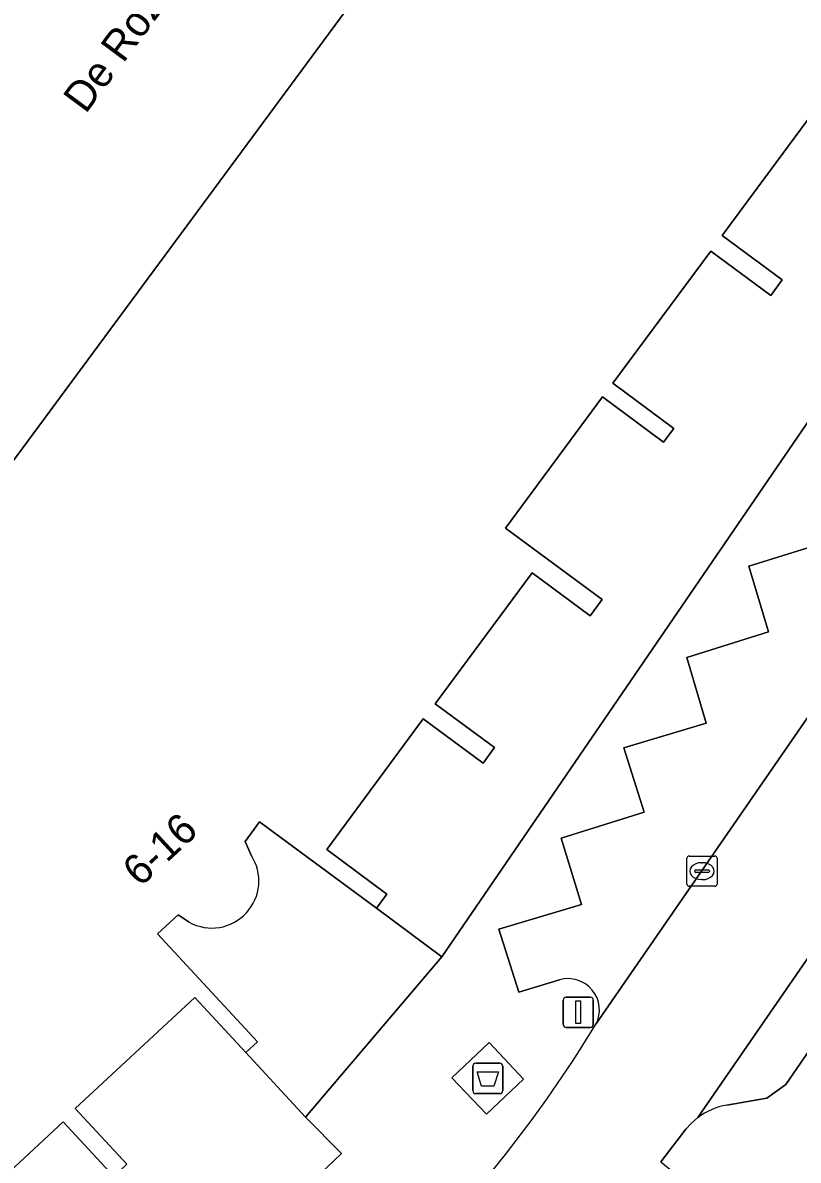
# Model space of a CAD drawing. Extents: x 161798 to 162385, y 382315 to 382833.
# Drawn here: x 161931.94 to 161957.55, y 382713.31 to 382750.85 of the extents above; entities that cross this region are included whole.
import ezdxf

# ---------------------------------------------------------------- set-up
doc = ezdxf.new("R2010")
doc.units = 0
for name, color, linetype in [('IMGEO_Afval_apart_plaats', 7, 'Continuous'), ('IMGEO_Erf', 7, 'Continuous'), ('IMGEO_Kolk', 7, 'Continuous'), ('IMGEO_Lichtmast', 7, 'Continuous'), ('IMGEO_Openbare_ruimte_label', 7, 'Continuous'), ('IMGEO_Pand', 7, 'Continuous'), ('IMGEO_Pand_nummerreeks', 7, 'Continuous'), ('IMGEO_Parkeervlak_open', 7, 'Continuous'), ('IMGEO_Rijbaan_lokaal_open', 7, 'Continuous'), ('IMGEO_Voetpad_gesloten', 7, 'Continuous'), ('IMGEO_Voetpad_open', 7, 'Continuous')]:
    doc.layers.add(name, color=color, linetype=linetype)

msp = doc.modelspace()

# ---------------------------------------------------------------- linework, layer by layer
at = {"layer": 'IMGEO_Afval_apart_plaats'}
for p, q in [((161946.804, 382715.605), (161946.804, 382716.405)), ((161946.804, 382716.405), (161946.804, 382715.605)), ((161946.904, 382716.505), (161947.694, 382716.505)), ((161947.694, 382716.505), (161946.904, 382716.505)), ((161947.794, 382716.405), (161947.794, 382715.605)), ((161947.794, 382715.605), (161947.794, 382716.405)), ((161947.694, 382715.505), (161946.904, 382715.505)), ((161946.904, 382715.505), (161947.694, 382715.505))]:
    msp.add_line(p, q, dxfattribs=at)
msp.add_lwpolyline([(161946.947, 382716.219), (161947.651, 382716.219), (161947.502, 382715.749), (161947.096, 382715.749), (161946.947, 382716.219)], dxfattribs=at)
for centre, start, end in [((161946.904, 382716.405), 90, 180), ((161946.904, 382716.405), 90, 180), ((161947.694, 382716.405), 0, 90), ((161947.694, 382716.405), 360, 90), ((161946.904, 382715.605), 180, 270), ((161946.904, 382715.605), 180, 270), ((161947.694, 382715.605), 270, 0), ((161947.694, 382715.605), 270, 0)]:
    msp.add_arc(centre, 0.1, start, end, dxfattribs=at)
at = {"layer": 'IMGEO_Erf'}
msp.add_lwpolyline([(161958.233, 382748.137), (161955.042, 382743.822), (161957.021, 382742.359), (161956.641, 382741.844), (161954.66, 382743.309), (161951.434, 382738.947), (161953.445, 382737.46), (161953.105, 382737.001), (161951.084, 382738.495), (161947.883, 382734.166), (161951.074, 382731.807), (161950.683, 382731.277), (161948.762, 382732.697), (161945.564, 382728.372), (161947.523, 382726.923), (161947.145, 382726.412), (161945.17, 382727.873), (161941.982, 382723.561), (161943.969, 382722.091), (161943.621, 382721.62), (161945.78, 382720.02), (161966.31, 382750)], dxfattribs=at)
msp.add_lwpolyline([(161939.315, 382716.857), (161937.63, 382718.675), (161933.68, 382715.013), (161935.385, 382713.173), (161934.95, 382712.77), (161933.281, 382714.571), (161929.281, 382710.864), (161930.963, 382709.05), (161930.526, 382708.645), (161927.829, 382711.555), (161923.886, 382707.901), (161925.58, 382706.073), (161925.148, 382705.673), (161923.428, 382707.528), (161919.49, 382703.878), (161921.21, 382702.023), (161920.781, 382701.625), (161922.903, 382699.334), (161925.083, 382696.984), (161942.474, 382713.523), (161941.286, 382714.73)], close=True, dxfattribs=at)
at = {"layer": 'IMGEO_Kolk'}
for p, q in [((161953.873, 382722.42), (161953.873, 382723.272)), ((161953.948, 382723.346), (161954.8, 382723.346)), ((161954.361, 382723.126), (161954.386, 382723.126)), ((161954.874, 382723.272), (161954.874, 382722.42)), ((161954.132, 382722.84), (161954.132, 382722.852)), ((161954.57, 382722.803), (161954.172, 382722.803)), ((161954.175, 382722.889), (161954.573, 382722.889)), ((161954.616, 382722.852), (161954.616, 382722.84)), ((161954.8, 382722.346), (161953.948, 382722.346)), ((161954.384, 382722.566), (161954.359, 382722.566))]:
    msp.add_line(p, q, dxfattribs=at)
for points in [[(161953.873, 382722.42), (161953.873, 382723.272)], [(161953.948, 382723.346), (161954.8, 382723.346)], [(161954.874, 382723.272), (161954.874, 382722.42)], [(161954.8, 382722.346), (161953.948, 382722.346)]]:
    msp.add_lwpolyline(points, dxfattribs=at)
for centre, radius, start, end in [((161953.95, 382723.27), 0.0765, 91.552, 178.448), ((161953.95, 382723.27), 0.0765, 91.552, 178.448), ((161954.798, 382723.27), 0.0765, 1.552, 88.448), ((161954.798, 382723.27), 0.0765, 1.552, 88.448), ((161954.172, 382722.849), 0.0403, 85.8775, 175.7526), ((161954.169, 382722.839), 0.0366, 178.938, 274.7102), ((161954.573, 382722.846), 0.043, 264.8664, 352.4533), ((161954.577, 382722.851), 0.0386, 1.7309, 96.639), ((161953.95, 382722.422), 0.0765, 181.552, 268.448), ((161953.95, 382722.422), 0.0765, 181.552, 268.448), ((161954.798, 382722.422), 0.0765, 271.552, 358.448), ((161954.798, 382722.422), 0.0765, 271.552, 358.448)]:
    msp.add_arc(centre, radius, start, end, dxfattribs=at)
for centre, major_axis, ratio, start_param, end_param in [((161954.36, 382722.846), (-0.387, 0.002), 0.722429, 4.712389, 7.853982), ((161954.385, 382722.846), (-0.39, 0.002), 0.717154, 1.570796, 4.712389)]:
    msp.add_ellipse(centre, major_axis=major_axis, ratio=ratio, start_param=start_param, end_param=end_param, dxfattribs=at)
at = {"layer": 'IMGEO_Lichtmast'}
for p, q in [((161949.792, 382717.789), (161949.792, 382718.589)), ((161949.792, 382718.589), (161949.792, 382717.789)), ((161949.892, 382718.689), (161950.682, 382718.689)), ((161950.682, 382718.689), (161949.892, 382718.689)), ((161950.782, 382718.589), (161950.782, 382717.789)), ((161950.782, 382717.789), (161950.782, 382718.589)), ((161950.682, 382717.689), (161949.892, 382717.689)), ((161949.892, 382717.689), (161950.682, 382717.689))]:
    msp.add_line(p, q, dxfattribs=at)
msp.add_lwpolyline([(161950.212, 382718.564), (161950.362, 382718.564), (161950.362, 382717.814), (161950.212, 382717.814), (161950.212, 382718.564)], dxfattribs=at)
for centre, start, end in [((161949.892, 382718.589), 90, 180), ((161949.892, 382718.589), 90, 180), ((161950.682, 382718.589), 0, 90), ((161950.682, 382718.589), 360, 90), ((161949.892, 382717.789), 180, 270), ((161949.892, 382717.789), 180, 270), ((161950.682, 382717.789), 270, 0), ((161950.682, 382717.789), 270, 0)]:
    msp.add_arc(centre, 0.1, start, end, dxfattribs=at)
at = {"layer": 'IMGEO_Pand'}
for points in [[(161967.663, 382756.723), (161954.083, 382766.765), (161941.685, 382750), (161929.946, 382734.127)], [(161939.486, 382723.371), (161939.284, 382723.823), (161939.764, 382724.472), (161943.621, 382721.62), (161943.969, 382722.091), (161941.982, 382723.561), (161945.17, 382727.873), (161947.145, 382726.412), (161947.523, 382726.923), (161945.564, 382728.372), (161948.762, 382732.697), (161950.683, 382731.277), (161951.074, 382731.807), (161947.883, 382734.166), (161951.084, 382738.495), (161953.105, 382737.001), (161953.445, 382737.46), (161951.434, 382738.947), (161954.66, 382743.309), (161956.641, 382741.844), (161957.021, 382742.359), (161955.042, 382743.822), (161958.233, 382748.137)], [(161926.013, 382729.602), (161909.25, 382714.065), (161920.781, 382701.625), (161921.21, 382702.023), (161919.49, 382703.878), (161923.428, 382707.528), (161925.148, 382705.673), (161925.58, 382706.073), (161923.886, 382707.901), (161927.829, 382711.555), (161930.526, 382708.645), (161930.963, 382709.05), (161929.281, 382710.864), (161933.281, 382714.571), (161934.95, 382712.77), (161935.385, 382713.173), (161933.68, 382715.013), (161937.63, 382718.675), (161939.315, 382716.857), (161939.696, 382717.21), (161936.39, 382720.776), (161937.071, 382721.407), (161937.444, 382721.159)]]:
    msp.add_lwpolyline(points, dxfattribs=at)
msp.add_arc((161938.189, 382722.519), 1.551, 241.2821, 33.2948, dxfattribs=at)
at = {"layer": 'IMGEO_Parkeervlak_open'}
for points in [[(161929.946, 382734.127), (161941.685, 382750), (161954.083, 382766.765), (161967.663, 382756.723), (161969.821, 382755.127), (161971.541, 382753.922), (161973.752, 382757.022), (161969.677, 382760.169), (161968.421, 382761.136), (161964.431, 382764.206), (161969.61, 382770.941), (161968.864, 382771.513), (161950.654, 382785.52), (161946.102, 382779.602), (161945.706, 382772.813), (161945.633, 382772.713), (161923.425, 382739.892), (161911.109, 382723.212), (161905.87, 382718.099), (161905.781, 382717.991)], [(161950.871, 382717.792), (161974.155, 382751.509)], [(161974.497, 382744.072), (161954.232, 382714.711)], [(161958.647, 382733.757), (161955.922, 382732.912), (161956.565, 382730.741), (161953.867, 382729.894), (161954.513, 382727.726), (161951.794, 382726.921), (161952.468, 382724.788), (161949.723, 382723.934), (161950.399, 382721.747), (161947.662, 382720.928), (161948.329, 382718.853), (161949.671, 382719.261)], [(161955.188, 382715.124), (161956.513, 382715.352), (161957.145, 382715.801), (161960.54, 382720.752)]]:
    msp.add_lwpolyline(points, dxfattribs=at)
for centre, radius, start, end in [((161949.95, 382718.265), 1.035, 332.8283, 105.6612), ((161955.555, 382712.961), 2.193, 99.6324, 127.0971)]:
    msp.add_arc(centre, radius, start, end, dxfattribs=at)
at = {"layer": 'IMGEO_Rijbaan_lokaal_open'}
msp.add_lwpolyline([(161953.014, 382713.254), (161953.841, 382714.33), (161954.011, 382714.515), (161954.232, 382714.711), (161974.497, 382744.072), (161975.012, 382744.815), (161978.57, 382749.833), (161978.687, 382750), (161978.946, 382750.365), (161982.788, 382755.905), (161991.783, 382769.02), (161988.335, 382771.671), (161988.086, 382771.315), (161983.272, 382764.558), (161979.867, 382759.641), (161975.168, 382752.813), (161974.155, 382751.509), (161950.871, 382717.792)], dxfattribs=at)
msp.add_arc((161913.61, 382740.517), 43.644, 316.3953, 328.6224, dxfattribs=at)
at = {"layer": 'IMGEO_Voetpad_gesloten'}
msp.add_lwpolyline([(161947.342, 382717.189), (161946.114, 382716.027), (161947.255, 382714.821), (161948.483, 382715.983)], close=True, dxfattribs=at)
at = {"layer": 'IMGEO_Voetpad_open'}
for points in [[(161988.086, 382771.315), (161988.335, 382771.671), (161985.47, 382773.783), (161980.996, 382767.347), (161973.752, 382757.022), (161971.541, 382753.922), (161969.821, 382755.127), (161966.31, 382750), (161945.78, 382720.02), (161941.286, 382714.73), (161942.474, 382713.523), (161925.083, 382696.984), (161927.394, 382694.49), (161927.839, 382694.207), (161928.944, 382695.23)], [(161949.671, 382719.261), (161948.329, 382718.853), (161947.662, 382720.928), (161950.399, 382721.747), (161949.723, 382723.934), (161952.468, 382724.788), (161951.794, 382726.921), (161954.513, 382727.726), (161953.867, 382729.894), (161956.565, 382730.741), (161955.922, 382732.912), (161958.647, 382733.757)], [(161937.444, 382721.159), (161937.071, 382721.407), (161936.39, 382720.776), (161939.696, 382717.21), (161939.315, 382716.857), (161941.286, 382714.73), (161945.78, 382720.02), (161943.621, 382721.62), (161939.764, 382724.472), (161939.284, 382723.823), (161939.486, 382723.371)], [(161960.54, 382720.752), (161957.145, 382715.801), (161956.513, 382715.352), (161955.188, 382715.124)], [(161954.232, 382714.711), (161954.011, 382714.515), (161953.841, 382714.33), (161953.014, 382713.254), (161953.428, 382712.907), (161950.594, 382709.807), (161950.225, 382710.144), (161949.878, 382709.799), (161949.605, 382709.468)]]:
    msp.add_lwpolyline(points, dxfattribs=at)
msp.add_lwpolyline([(161947.342, 382717.189), (161948.483, 382715.983), (161947.255, 382714.821), (161946.114, 382716.027)], close=True, dxfattribs=at)
for centre, radius, start, end in [((161938.189, 382722.519), 1.551, 241.2821, 33.2948), ((161949.95, 382718.265), 1.035, 332.8283, 105.6612), ((161913.61, 382740.517), 43.644, 316.3953, 328.6224), ((161955.555, 382712.961), 2.193, 99.6324, 127.0971)]:
    msp.add_arc(centre, radius, start, end, dxfattribs=at)

# ---------------------------------------------------------------- texts
at = {"layer": 'IMGEO_Openbare_ruimte_label'}
msp.add_text('De Rozentuin', height=1, rotation=53.4967, dxfattribs=at).set_placement((161934.021, 382747.812))
at = {"layer": 'IMGEO_Pand_nummerreeks'}
msp.add_text('6-16', height=1, rotation=42.8175, dxfattribs=at).set_placement((161935.823, 382722.295))

doc.saveas('drawing.dxf')
